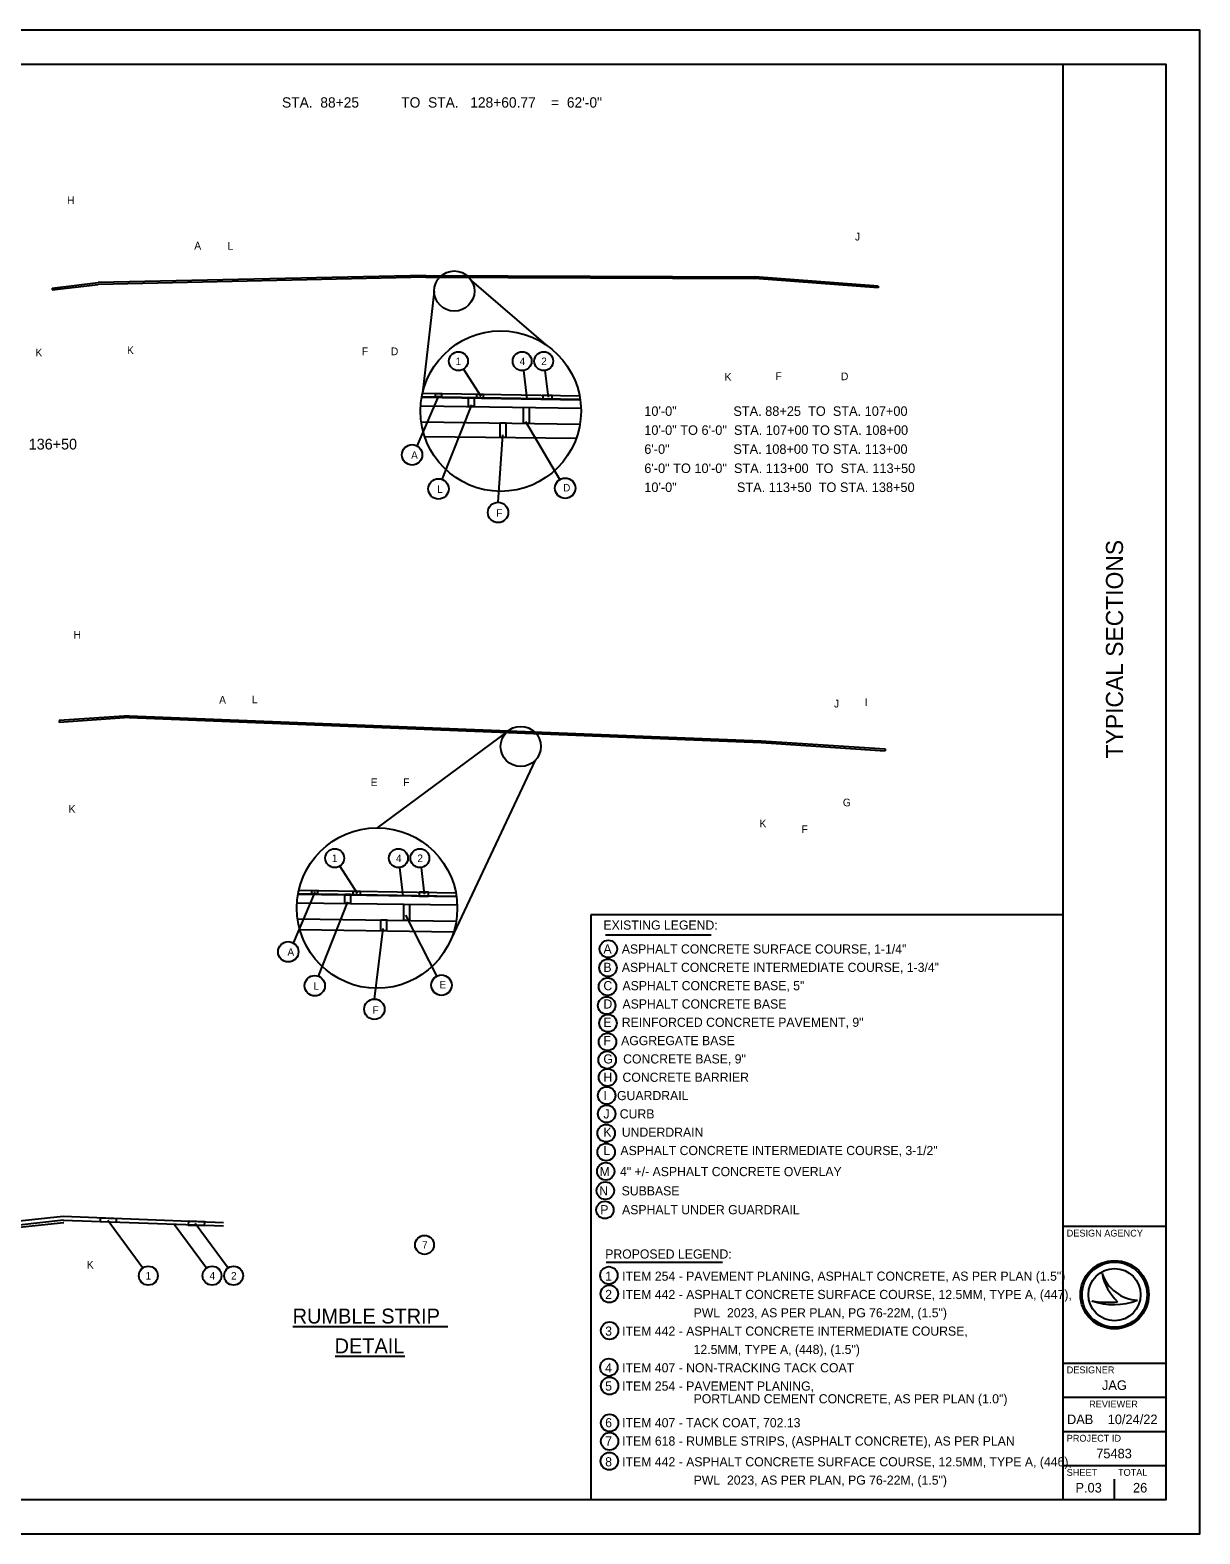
# Model space of a CAD drawing. Extents: x -210 to 558, y -150 to 205.
# Drawn here: x 88.1 to 173.7, y -4.5 to 105.5 of the extents above; entities that cross this region are included whole.
import ezdxf

# ---------------------------------------------------------------- set-up
doc = ezdxf.new("R2010")
doc.units = 0
for name, color, linetype in [('Level 1', 7, 'Continuous'), ('Level 3', 7, 'Continuous'), ('Level 59', 7, 'Continuous'), ('SH_Border', 7, 'Continuous'), ('SH_Cut_Line', 7, 'Continuous'), ('SH_Data', 7, 'Continuous')]:
    doc.layers.add(name, color=color, linetype=linetype)

msp = doc.modelspace()

# ---------------------------------------------------------------- linework, layer by layer
at = {"layer": 'Level 1'}
for p, q in [((89.71, 86.65), (93.08, 87.05)), ((89.71, 86.52), (93.09, 86.91)), ((117.06, 87.57), (93.08, 87.05)), ((117.06, 87.44), (93.09, 86.91)), ((117.06, 87.57), (141.14, 87.48)), ((117.06, 87.44), (141.13, 87.34)), ((120.4, 87.18), (125.8, 82.53)), ((150.15, 86.67), (141.13, 87.34)), ((150.15, 86.8), (141.14, 87.48)), ((89.71, 86.65), (89.71, 86.52)), ((117.67, 86.43), (116.82, 78.97)), ((150.15, 86.8), (150.15, 86.67)), ((119.81, 80.72), (121.07, 78.75)), ((124.19, 80.61), (124.44, 78.55)), ((125.76, 80.61), (126, 78.66)), ((116.43, 75.09), (118.01, 78.77)), ((116.77, 78.72), (128.34, 78.53)), ((116.77, 78.72), (128.34, 78.53)), ((116.77, 78.72), (128.34, 78.53)), ((116.81, 78.67), (128.34, 78.48)), ((116.82, 78.95), (128.35, 78.77)), ((116.82, 78.95), (128.35, 78.77)), ((116.68, 78.04), (128.41, 77.87)), ((118.25, 72.65), (120.42, 78.1)), ((116.72, 76.87), (128.33, 76.69)), ((122.34, 70.99), (122.69, 75.91)), ((126.87, 72.65), (124.37, 76.87)), ((116.97, 75.8), (128.06, 75.66)), ((95.34, 55.36), (90.23, 55.02)), ((95.34, 55.23), (90.23, 54.88)), ((90.23, 55.02), (90.23, 54.88)), ((95.34, 55.36), (141.59, 53.54)), ((95.34, 55.23), (141.58, 53.41)), ((122.96, 54.16), (113.5, 47.17)), ((141.58, 53.41), (150.67, 52.81)), ((141.59, 53.54), (150.67, 52.94)), ((150.67, 52.94), (150.67, 52.81)), ((125.06, 52.11), (118.71, 38.63)), ((110.76, 44.37), (112.02, 42.4)), ((115.13, 44.27), (115.38, 42.2)), ((116.71, 44.27), (116.94, 42.31)), ((107.37, 38.74), (108.95, 42.45)), ((107.72, 42.37), (119.29, 42.18)), ((107.72, 42.37), (119.29, 42.18)), ((107.76, 42.6), (119.29, 42.42)), ((107.76, 42.32), (119.29, 42.14)), ((107.63, 41.69), (119.35, 41.53)), ((109.2, 36.31), (111.36, 41.75)), ((117.86, 36.33), (115.59, 40.77)), ((107.67, 40.52), (119.28, 40.35)), ((107.84, 39.72), (119.09, 39.57)), ((113.29, 34.64), (113.94, 39.81)), ((90.51, 18.74), (87.09, 18.38)), ((102.26, 18.27), (90.51, 18.74)), ((90.54, 18.46), (87.09, 18.09)), ((90.56, 18.27), (87.09, 17.9)), ((102.25, 18.02), (90.51, 18.45)), ((96.34, 14.96), (93.78, 18.44)), ((101, 14.96), (98.65, 18.15)), ((102.58, 14.96), (100.17, 18.22))]:
    msp.add_line(p, q, dxfattribs=at)
for points in [[(117.77, 78.93), (118.19, 78.93), (118.19, 78.69), (117.77, 78.7)], [(120.18, 78.66), (120.6, 78.65), (120.6, 77.98), (120.18, 77.99)], [(120.79, 78.89), (121.25, 78.88), (121.24, 78.6), (120.78, 78.6)], [(125.61, 78.53), (126.31, 78.52), (126.31, 78.8), (125.62, 78.81)], [(124.19, 77.93), (124.61, 77.92), (124.61, 76.75), (124.19, 76.76)], [(122.49, 76.78), (122.91, 76.78), (122.91, 75.73), (122.49, 75.73)], [(108.72, 42.59), (109.14, 42.58), (109.14, 42.35), (108.72, 42.35)], [(111.13, 42.32), (111.55, 42.31), (111.55, 41.64), (111.13, 41.65)], [(111.73, 42.54), (112.26, 42.53), (112.26, 42.25), (111.73, 42.26)], [(116.56, 42.18), (117.25, 42.17), (117.26, 42.45), (116.56, 42.46)], [(115.45, 41.58), (115.87, 41.57), (115.87, 40.4), (115.45, 40.41)], [(113.76, 40.43), (114.18, 40.43), (114.18, 39.63), (113.76, 39.64)], [(94.39, 18.31), (93.25, 18.35), (93.26, 18.63), (94.4, 18.59)], [(99.67, 18.11), (100.87, 18.07), (100.88, 18.35), (99.68, 18.39)]]:
    msp.add_lwpolyline(points, close=True, dxfattribs=at)
for centre, radius in [((119.14, 86.43), 1.47), ((122.54, 77.65), 5.87), ((122.54, 77.65), 5.87), ((119.44, 81.3), 0.691), ((124.1, 81.3), 0.691), ((125.68, 81.3), 0.691), ((116.05, 74.45), 0.746), ((117.98, 71.96), 0.746), ((127.25, 72.01), 0.746), ((122.34, 70.24), 0.746), ((124, 53.12), 1.47), ((113.49, 41.3), 5.87), ((110.39, 44.95), 0.691), ((115.05, 44.95), 0.691), ((116.62, 44.95), 0.691), ((106.99, 38.1), 0.746), ((108.93, 35.62), 0.746), ((118.2, 35.66), 0.746), ((113.29, 33.9), 0.746), ((116.96, 16.66), 0.691), ((96.75, 14.41), 0.691), ((101.41, 14.41), 0.691), ((102.99, 14.41), 0.691)]:
    msp.add_circle(centre, radius, dxfattribs=at)
at = {"layer": 'Level 59'}
for p, q in [((130.19, 39.34), (137.93, 39.34)), ((130.25, 15.4), (138.76, 15.4)), ((107.33, 10.7), (118.66, 10.7)), ((110.42, 8.53), (115.52, 8.53))]:
    msp.add_line(p, q, dxfattribs=at)
for centre in [(130.41, 38.31), (130.38, 36.93), (130.35, 35.55), (130.29, 34.17), (130.38, 32.88), (130.35, 31.51), (130.32, 30.19), (130.35, 28.91), (130.29, 27.59), (130.29, 26.25), (130.25, 24.83), (130.25, 23.45), (130.22, 22.04), (130.19, 20.63), (130.16, 19.22), (130.45, 14.43), (130.48, 13.08), (130.5, 10.39), (130.45, 7.71), (130.5, 6.35), (130.5, 3.64), (130.5, 2.29), (130.48, 0.84)]:
    msp.add_circle(centre, 0.639, dxfattribs=at)
at = {"layer": 'SH_Border'}
for p, q in [((163.7, -1.98), (163.7, 103.02)), ((163.7, 18.02), (171.2, 18.02)), ((163.7, 8.02), (171.2, 8.02)), ((163.7, 5.52), (171.2, 5.52)), ((163.7, 3.02), (171.2, 3.02)), ((163.7, 0.52), (171.2, 0.52))]:
    msp.add_line(p, q, dxfattribs=at)
msp.add_lwpolyline([(11.2, 103.02), (171.2, 103.02), (171.2, -1.98), (11.2, -1.98)], close=True, dxfattribs=at)
at = {"layer": 'SH_Cut_Line'}
msp.add_lwpolyline([(3.7, -4.48), (173.7, -4.48), (173.7, 105.52), (3.7, 105.52)], close=True, dxfattribs=at)
at = {"layer": 'SH_Data'}
for p, q in [((163.7, 40.8), (129.14, 40.8)), ((129.14, 40.8), (129.14, -1.98)), ((166.53, 14.57), (166.53, 14.57)), ((165.78, 12.57), (165.78, 12.57)), ((167.45, 13.02), (167.45, 13.02)), ((169.13, 12.61), (169.13, 12.61)), ((167.45, -1.98), (167.45, -0.48)), ((165.57, -1.1), (165.57, -1.1))]:
    msp.add_line(p, q, dxfattribs=at)
for radius in [2.5, 2.38, 2.38, 1.91]:
    msp.add_circle((167.45, 13.02), radius, dxfattribs=at)
for centre, radius, start, end in [((169.28, 15.51), 2.9, 198.9257, 198.9319), ((170.43, 15.37), 3.98, 191.6379, 191.6421), ((169.28, 15.51), 2.9, 198.9319, 267.1657), ((170.43, 15.37), 3.98, 191.6421, 226.0947), ((167.39, 17.37), 5.07, 251.4576, 290.0832), ((166.94, 18.79), 6.33, 259.4964, 259.4995), ((167.39, 17.37), 5.07, 251.4527, 251.4576), ((166.94, 18.79), 6.33, 259.4995, 276.6672)]:
    msp.add_arc(centre, radius, start, end, dxfattribs=at)

# ---------------------------------------------------------------- texts
at = {"layer": 'Level 1'}
for s, p in [('1', (119.24, 81.02)), ('4', (123.92, 81.02)), ('2', (125.5, 81.02)), ('1', (110.18, 44.67)), ('4', (114.87, 44.67)), ('2', (116.44, 44.67)), ('7', (116.78, 16.38)), ('1', (96.55, 14.13)), ('4', (101.23, 14.13)), ('2', (102.8, 14.13))]:
    msp.add_text(s, height=0.547, dxfattribs=at).set_placement(p)
at = {"layer": 'Level 3'}
for s, p in [('H', (90.8, 92.79)), ('J', (148.46, 90.13)), ('A', (100.11, 89.47)), ('L', (102.55, 89.45)), ('K', (88.49, 81.65)), ('K', (95.19, 81.82)), ('F', (112.37, 81.74)), ('D', (114.5, 81.74)), ('K', (138.92, 79.87)), ('F', (142.65, 79.93)), ('D', (147.43, 79.91)), ('H', (91.28, 61.01)), ('A', (101.93, 56.25)), ('L', (104.33, 56.28)), ('J', (146.92, 55.97)), ('I', (149.17, 56.09)), ('E', (113.02, 50.22)), ('F', (115.4, 50.22)), ('K', (90.92, 48.27)), ('G', (147.57, 48.74)), ('K', (141.47, 47.2)), ('F', (144.55, 46.78)), ('K', (92.25, 14.93))]:
    msp.add_text(s, height=0.562, dxfattribs=at).set_placement(p)
at = {"layer": 'Level 59'}
for s, height, p in [('STA.  88+25           TO  STA.   128+60.77    =  62\'-0"', 0.7548, (106.53, 99.85)), ('10\'-0"                STA. 88+25  TO  STA. 107+00', 0.697, (133.04, 77.3)), ('10\'-0" TO 6\'-0"  STA. 107+00 TO STA. 108+00', 0.697, (133.04, 75.91)), ('STA.  88+25     TO  STA.   136+50', 0.7854, (75.42, 74.84)), ('6\'-0"                  STA. 108+00 TO STA. 113+00', 0.697, (133.04, 74.52)), ('A', 0.547, (115.98, 74.16)), ('6\'-0" TO 10\'-0"  STA. 113+00  TO  STA. 113+50', 0.697, (133.04, 73.12)), ('L', 0.547, (117.89, 71.67)), ('D', 0.547, (127.1, 71.77)), ('10\'-0"                 STA. 113+50  TO STA. 138+50', 0.697, (133.04, 71.73)), ('F', 0.547, (122.21, 69.92)), ('EXISTING LEGEND:', 0.6698, (130.05, 39.72)), ('A   ASPHALT CONCRETE SURFACE COURSE, 1-1/4"', 0.6698, (130.05, 37.97)), ('A', 0.547, (106.93, 37.81)), ('B   ASPHALT CONCRETE INTERMEDIATE COURSE, 1-3/4"', 0.6698, (130.05, 36.63)), ('L', 0.547, (108.84, 35.33)), ('E', 0.547, (118.05, 35.42)), ('C   ASPHALT CONCRETE BASE, 5"', 0.6698, (130.05, 35.29)), ('F', 0.547, (113.15, 33.57)), ('D   ASPHALT CONCRETE BASE', 0.6698, (130.05, 33.95)), ('E   REINFORCED CONCRETE PAVEMENT, 9"', 0.6698, (130.05, 32.61)), ('F   AGGREGATE BASE', 0.6698, (130.05, 31.27)), ('G   CONCRETE BASE, 9"', 0.6698, (130.05, 29.93)), ('H   CONCRETE BARRIER', 0.6698, (130.05, 28.59)), ('I   GUARDRAIL ', 0.6698, (130.05, 27.25)), ('J   CURB', 0.67, (130.05, 25.91)), ('K   UNDERDRAIN ', 0.6698, (130.05, 24.57)), ('L   ASPHALT CONCRETE INTERMEDIATE COURSE, 3-1/2"          ', 0.6698, (130.05, 23.23)), ('M   4" +/- ASPHALT CONCRETE OVERLAY   ', 0.6698, (129.77, 21.69)), ('N    SUBBASE', 0.6698, (129.74, 20.28)), ('P    ASPHALT UNDER GUARDRAIL', 0.6698, (129.82, 18.9)), ('PROPOSED LEGEND:', 0.6698, (130.18, 15.66)), ('1   ITEM 254 - PAVEMENT PLANING, ASPHALT CONCRETE, AS PER PLAN (1.5")', 0.6698, (130.18, 14.04)), ('2   ITEM 442 - ASPHALT CONCRETE SURFACE COURSE, 12.5MM, TYPE A, (447),', 0.6698, (130.18, 12.7)), ('RUMBLE STRIP', 1.0907, (107.31, 10.91)), ('                          PWL  2023, AS PER PLAN, PG 76-22M, (1.5")', 0.6698, (130.18, 11.36)), ('3   ITEM 442 - ASPHALT CONCRETE INTERMEDIATE COURSE,', 0.6698, (130.18, 10.02)), ('DETAIL', 1.091, (110.38, 8.73)), ('                          12.5MM, TYPE A, (448), (1.5")', 0.6698, (130.18, 8.68)), ('4   ITEM 407 - NON-TRACKING TACK COAT', 0.6698, (130.18, 7.34)), ('5   ITEM 254 - PAVEMENT PLANING, ', 0.6698, (130.18, 6)), ('                          PORTLAND CEMENT CONCRETE, AS PER PLAN (1.0")', 0.6698, (130.18, 5.07)), ('6   ITEM 407 - TACK COAT, 702.13', 0.6698, (130.18, 3.32)), ('7   ITEM 618 - RUMBLE STRIPS, (ASPHALT CONCRETE), AS PER PLAN', 0.6698, (130.18, 1.98)), ('8   ITEM 442 - ASPHALT CONCRETE SURFACE COURSE, 12.5MM, TYPE A, (446),', 0.6698, (130.18, 0.46)), ('                          PWL  2023, AS PER PLAN, PG 76-22M, (1.5")', 0.6698, (130.18, -0.88))]:
    msp.add_text(s, height=height, dxfattribs=at).set_placement(p)
at = {"layer": 'SH_Data'}
msp.add_text('TYPICAL SECTIONS', height=1.25, rotation=90, dxfattribs=at).set_placement((168.07, 52.25))
for s, height, p in [('DESIGN AGENCY', 0.5, (163.95, 17.27)), ('DESIGNER', 0.5, (163.95, 7.27)), ('JAG', 0.7, (166.53, 6.05)), ('REVIEWER', 0.5, (165.59, 4.77)), ('DAB', 0.7, (163.97, 3.55)), ('10/24/22', 0.7, (166.95, 3.55)), ('PROJECT ID', 0.5, (163.95, 2.27)), ('75483', 0.7, (166.11, 1.05)), ('SHEET', 0.5, (163.95, -0.23)), ('TOTAL', 0.5, (167.7, -0.23)), ('P.03', 0.7, (164.59, -1.45)), ('26', 0.7, (168.8, -1.45))]:
    msp.add_text(s, height=height, dxfattribs=at).set_placement(p)

doc.saveas('drawing.dxf')
